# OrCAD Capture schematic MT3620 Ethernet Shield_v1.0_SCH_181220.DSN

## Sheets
1 01 Title, Revision History: rev: v1.0
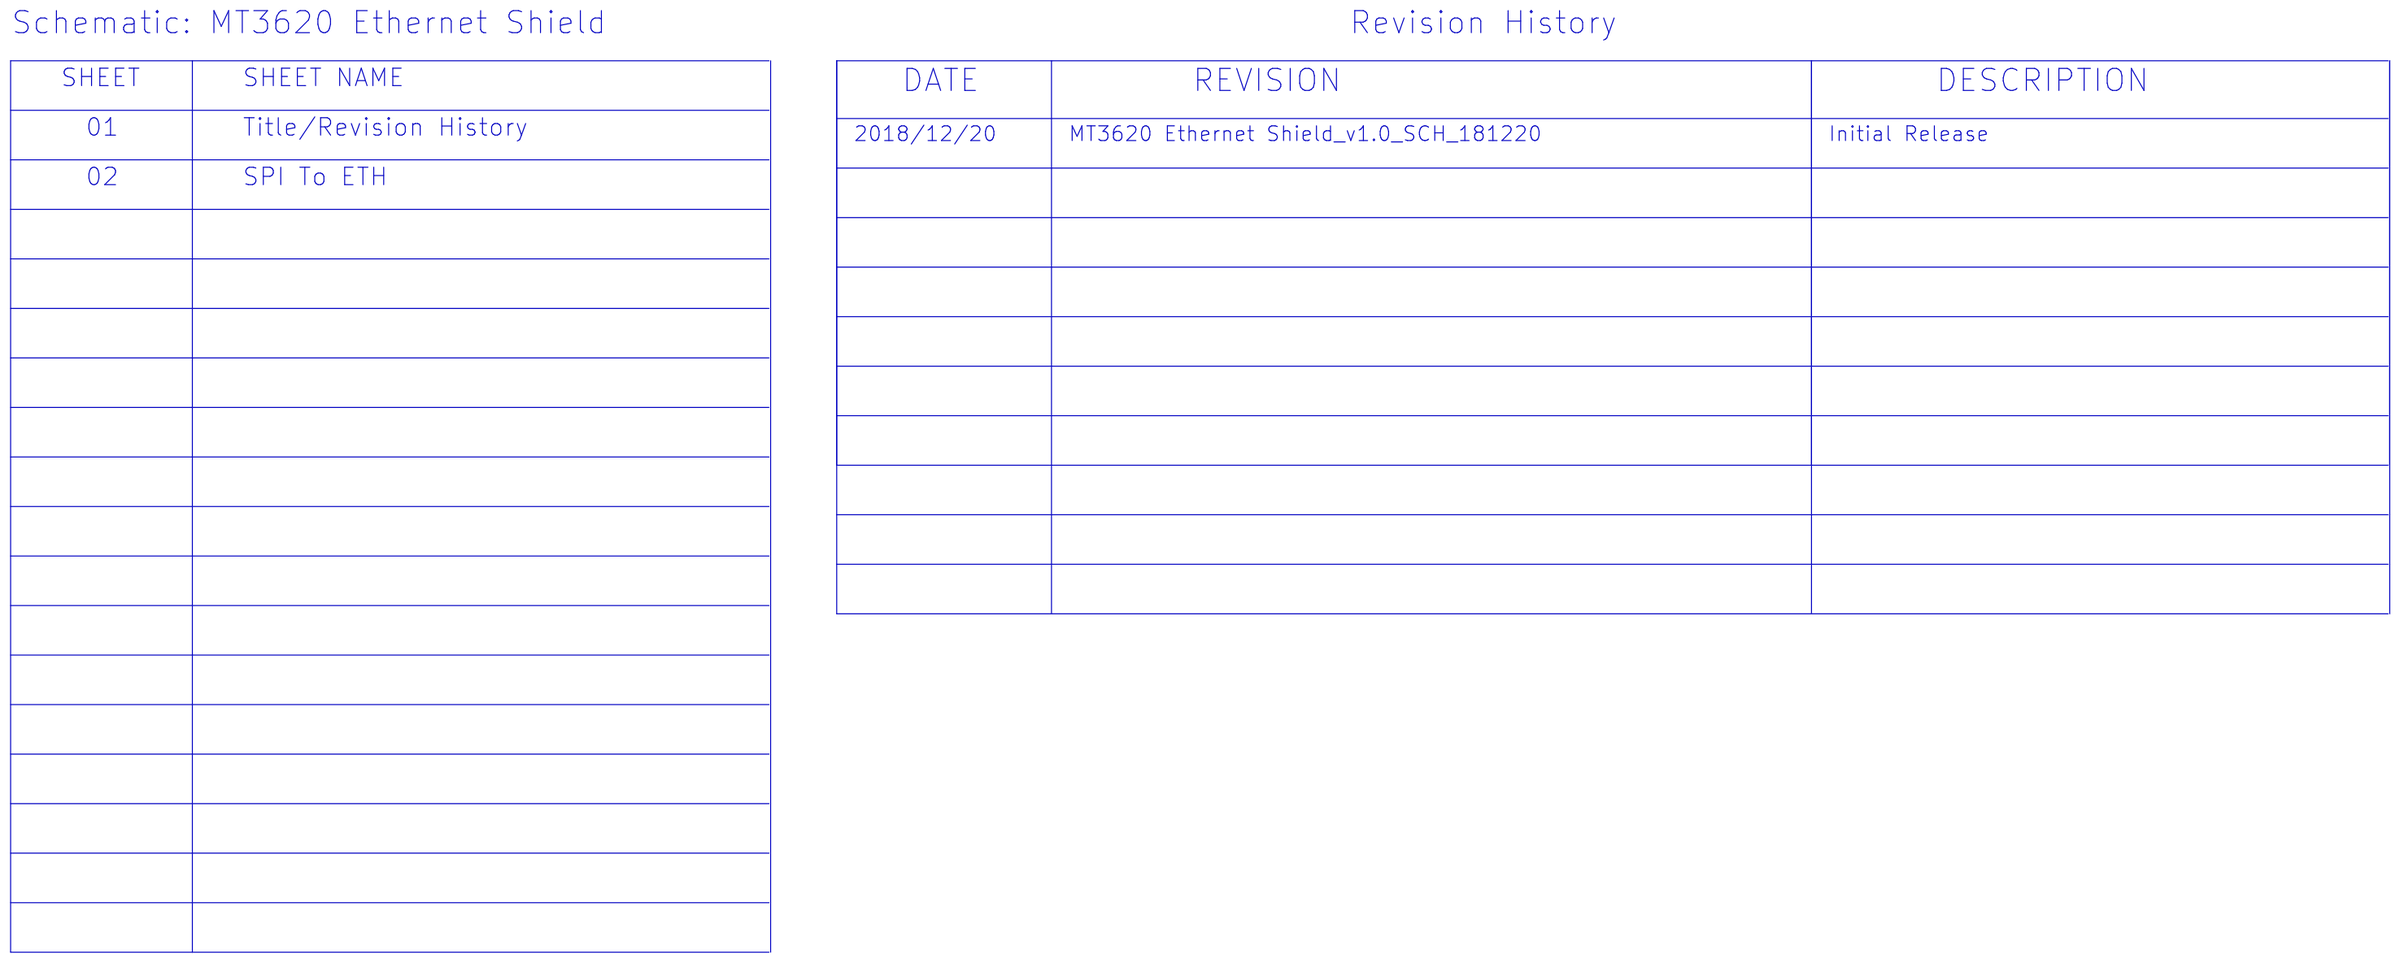
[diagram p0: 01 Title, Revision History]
2 02 SPI To ETH: size A3
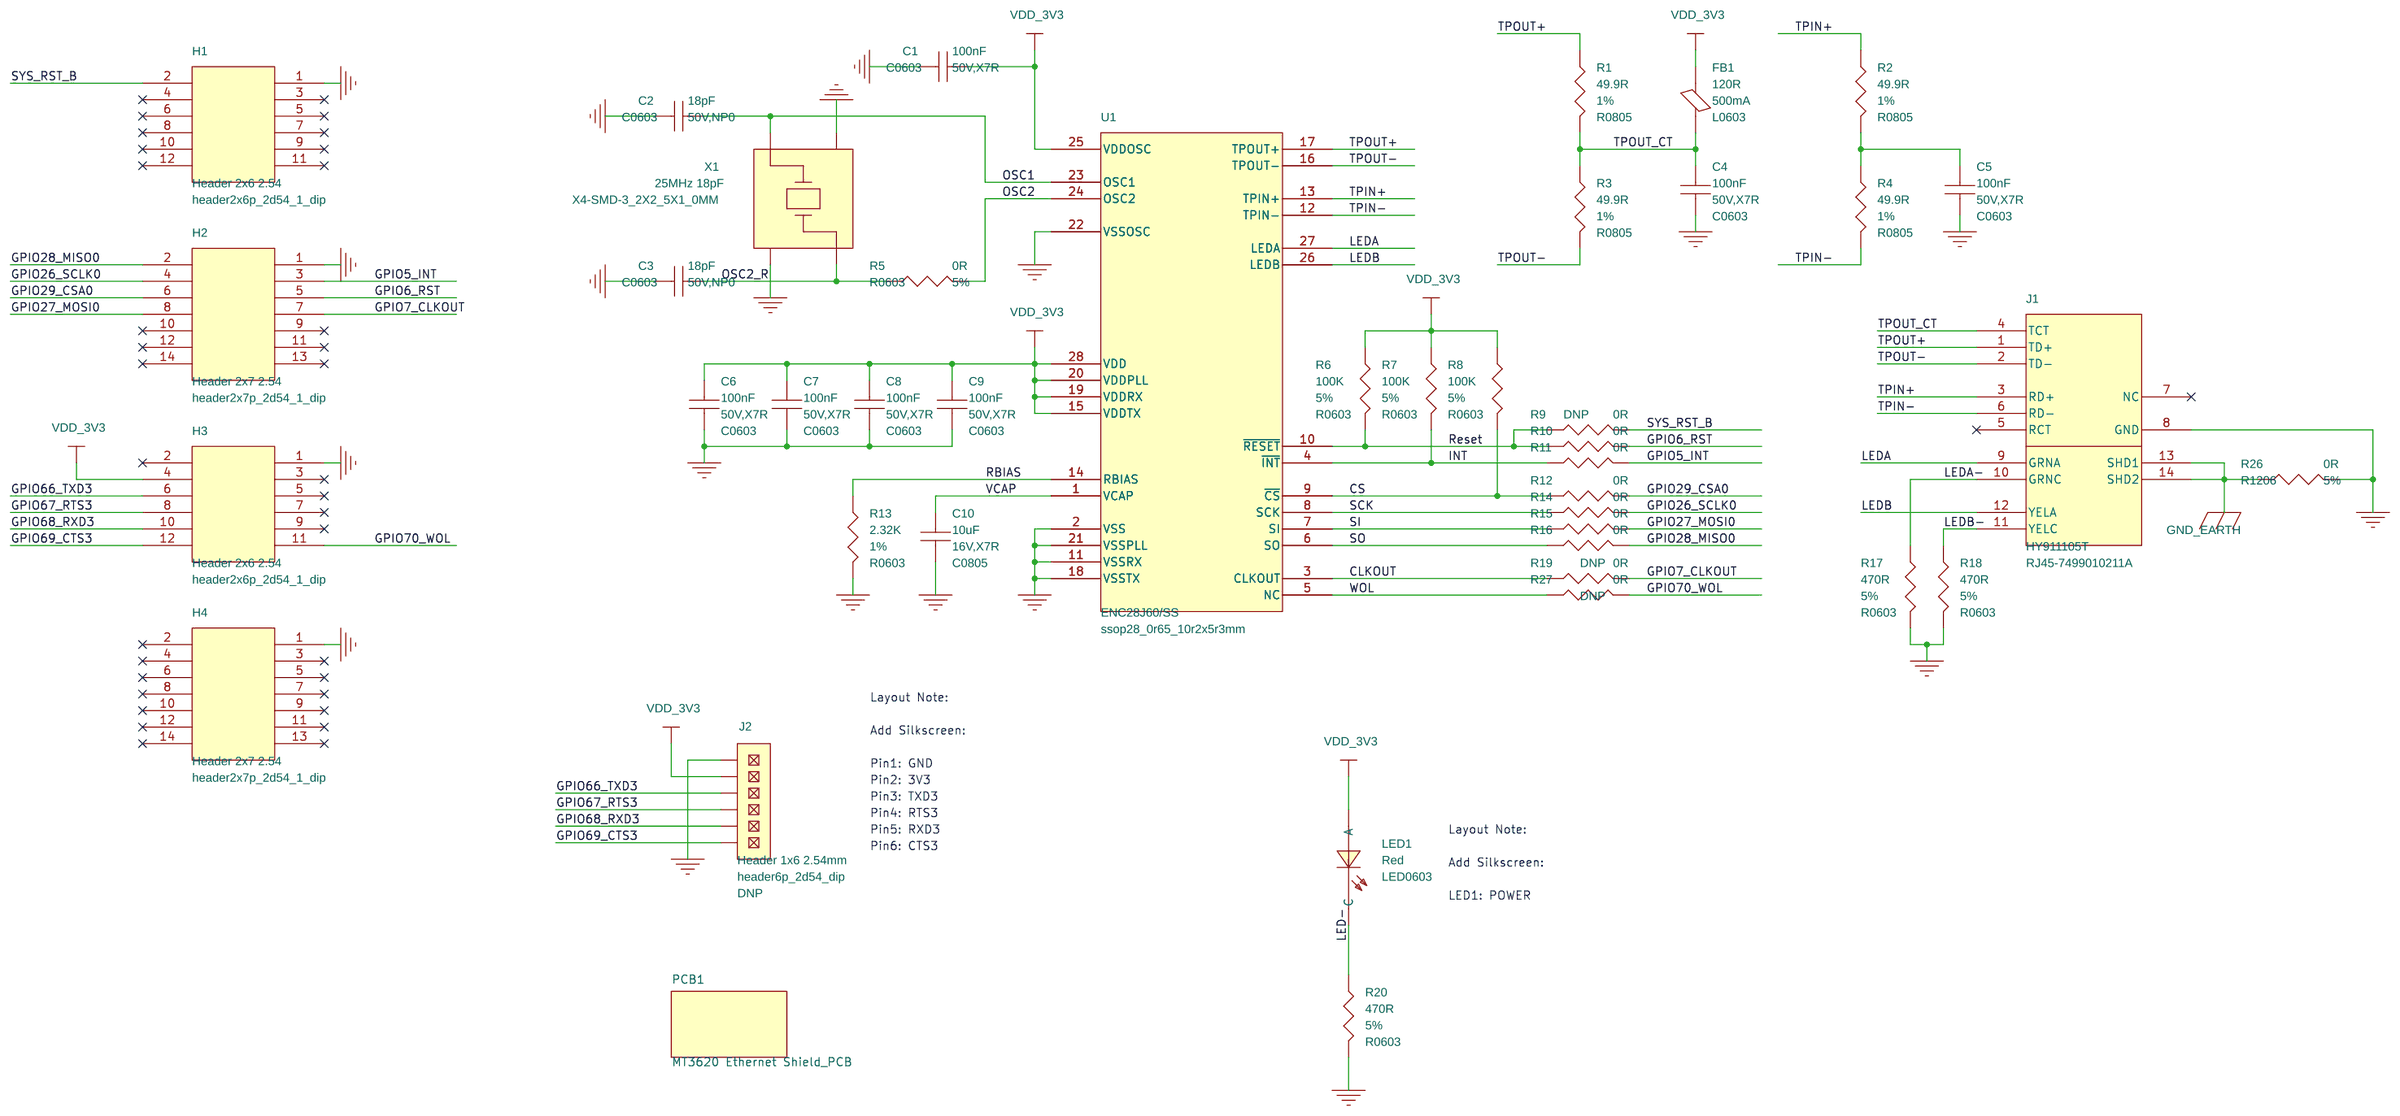
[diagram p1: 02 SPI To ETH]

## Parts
C1  100nF  [C0603]
C2  18pF  [C0603]
C3  18pF  [C0603]
C4  100nF  [C0603]
C5  100nF  [C0603]
C6  100nF  [C0603]
C7  100nF  [C0603]
C8  100nF  [C0603]
C9  100nF  [C0603]
C10  10uF  [C0805]
FB1  120R  [L0603]
H1  Header 2x6 2.54  [header2x6p_2d54_1_dip]
H2  Header 2x7 2.54  [header2x7p_2d54_1_dip]
H3  Header 2x6 2.54  [header2x6p_2d54_1_dip]
H4  Header 2x7 2.54  [header2x7p_2d54_1_dip]
J1  HY911105T  [RJ45-7499010211A]
J2  Header 1x6 2.54mm  [header6p_2d54_dip]
LED1  Red  [LED0603]
PCB1  MT3620 Ethernet Shield_PCB  [NA]
R1  49.9R  [R0805]
R2  49.9R  [R0805]
R3  49.9R  [R0805]
R4  49.9R  [R0805]
R5  0R  [R0603]
R6  100K  [R0603]
R7  100K  [R0603]
R8  100K  [R0603]
R9  0R  [R0603]
R10  0R  [R0603]
R11  0R  [R0603]
R12  0R  [R0603]
R13  2.32K  [R0603]
R14  0R  [R0603]
R15  0R  [R0603]
R16  0R  [R0603]
R17  470R  [R0603]
R18  470R  [R0603]
R19  0R  [R0603]
R20  470R  [R0603]
R26  0R  [R1206]
R27  0R  [R0603]
U1  ENC28J60/SS  [ssop28_0r65_10r2x5r3mm]
X1  25MHz 18pF  [X4-SMD-3_2X2_5X1_0MM]

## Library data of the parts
C1 C4-C9 = CC: SMD CAP Ceramic 100nF-50V-10%-X7R;0603; Manufacturer Part Number: YAGEO;CC0603KRX7R9BB104; PN: 302010138; Part Type: Ceramic; Rating: 50V,X7R; Status: BeagleBone Carrier Board
C2 C3 = CC: SMD CAP Ceramic 18pF-50V-5%-NPO;0603; Manufacturer Part Number: YAGEO;CC0603JRNPO9BN180; PN: 302010083; Part Type: Ceramic; Rating: 50V,NP0; Status: Grove X Gateway
C10 = CC: SMD CAP Ceramic 10uF-16V-10%-X7R;0805; Manufacturer Part Number: YAGEO;CC0805MKX7R7BB106; PN: 302011546; Part Type: Ceramic; Rating: 16V,X7R; Status: Grove X Gateway
FB1 = FB: SMD Ferrite Bead 120R-500mA;0603; Manufacturer Part Number: Murata;BLM18AG121SN1D; PN: 303030001; Part Type: Ferrite Bead; Rating: 500mA; Status: BeagleBone Carrier Board
H1 H3 = Header_2x6: DIP Black Female Header;2*6P-2.54-8.5-10.5; Manufacturer Part Number: 思拓展;FH-2.54-8.5-PC104-2*6P-PBT; PN: 320030886; Part Type: Header; Status: MT3620 Ethernet Shield
H2 H4 = Header_2x7: DIP Black Female Header;2*7P-2.54-8.5-10.5; Manufacturer Part Number: 思拓展;FH-2.54-8.5-PC104-2*7P-PBT; PN: 320030887; Part Type: Header; Status: MT3620 Ethernet Shield
J1 = RJ45_HanRun_HY911105T: DIP RJ45 W/P;12P-21.3*16.04*13.5mm; Manufacturer Part Number: 汉仁;HY911105T; PN: 320140014; Part Type: RJ45; Status: Azure Sphere Ethernet Shield
J2 = Header_1x6: DIP Black Male Header VERT;1*6P-2.54-2.54-11.6/3.0mm; ASSY: DNP; Manufacturer Part Number: P125-1106A1BS116A1; PN: 320020078; Part Type: Header; Status: BeagleBone Carrier Board
LED1 = Single_LED: SMD LED Clear-Red;LED-0603; Manufacturer Part Number: Everlight;EL-19-217/R6C-AL1M2VY/3T(正贴); PN: 304090042; Part Type: LED; Status: BeagleBone Carrier Board
PCB1 = PCB: PCB;MT3620 Ethernet Shield_v1.0-哑光黑油白字-2层; Manufacturer Part Number: 化学沉金-69*50*1.6mm; PN: 319013391
R1-R4 = R: SMD RES 49.9R-1%-1/8W;0805; Manufacturer Part Number: YAGEO;RC0805FR-0749R9L; PN: 301010339; Part Type: RES; Rating: 1%; Status: Azure Sphere Ethernet Shield
R5 R10-R12 R14-R16 = R: SMD RES 0R-5%-1/10W;0603; Manufacturer Part Number: YAGEO;RC0603JR-070RL; PN: 301010292; Part Type: RES; Rating: 5%
R6-R8 = R: SMD RES 100K-5%-1/10W;0603; Manufacturer Part Number: YAGEO;RC0603JR-07100KL; PN: 301010089; Part Type: RES; Rating: 5%; Status: Grove X Gateway
R9 R19 R27 = R: SMD RES 0R-5%-1/10W;0603; ASSY: DNP; Manufacturer Part Number: YAGEO;RC0603JR-070RL; PN: 301010292; Part Type: RES; Rating: 5%
R13 = R: SMD RES 2.32K-1%-1/10W;0603; Manufacturer Part Number: YAGEO;RC0603FR-072K32L; PN: 301012382; Part Type: RES; Rating: 1%; Status: Azure Sphere Ethernet Shield
R17 R18 R20 = R: SMD RES 470R-5%-1/10W;0603; Manufacturer Part Number: YAGEO;RC0603JR-07470RL; PN: 301010088; Part Type: RES; Rating: 5%; Status: IOT Enabling Dongle Board
R26 = R: SMD RES 0R-5%-1/4W;1206; Manufacturer Part Number: YAGEO;RC1206JR-070RL; PN: 301010407; Part Type: RES; Rating: 5%; Status: BeagleBone Carrier Board
U1 = ENC28J60: SMD IC;Stand-Alone Ethernet Controller with SPI Interface;SSOP-28; Manufacturer Part Number: Microchip;ENC28J60/SS; PN: 310070728; Part Type: Transceiver; Status: Azure Sphere Ethernet Shield
X1 = XTAL_4P: SMD Crystal 25MHz-18pF-30ppm;4P-SMD-L3.2*W2.5*H0.8mm; Manufacturer Part Number: Kyocera;CX3225GB25000P0HPQCC; PN: 306010744; Part Type: Crystal; Rating: 30ppm; Status: Combox Pro

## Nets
GND: C1.1 C2.1 C3.1 C4.2 C5.2 C6.2 C7.2 C8.2 C9.2 C10.2 H1.1 H2.1 H3.1 H4.1 J1.8(GND) J2.1 R13.2 R17.2 R18.2 R20.2 R26.2 U1.2(VSS) U1.11(VSSRX) U1.18(VSSTX) U1.21(VSSPLL) U1.22(VSSOSC) X1.2 X1.4
GND_EARTH: J1.13(SHD1) J1.14(SHD2) R26.1
VDD_3V3: C1.2 C6.1 C7.1 C8.1 C9.1 FB1.2 H3.4 J2.2 LED1.1(A) R6.1 R7.1 R8.1 U1.15(VDDTX) U1.19(VDDRX) U1.20(VDDPLL) U1.25(VDDOSC) U1.28(VDD)
CLKOUT: R19.1 U1.3(CLKOUT)
CS: R8.2 R12.1 U1.9(~{CS})
GPIO5_INT: H2.3 R11.2
GPIO6_RST: H2.5 R10.2
GPIO7_CLKOUT: H2.7 R19.2
GPIO26_SCLK0: H2.4 R14.2
GPIO27_MOSI0: H2.8 R15.2
GPIO28_MISO0: H2.2 R16.2
GPIO29_CSA0: H2.6 R12.2
GPIO66_TXD3: H3.6 J2.3
GPIO67_RTS3: H3.8 J2.4
GPIO68_RXD3: H3.10 J2.5
GPIO69_CTS3: H3.12 J2.6
GPIO70_WOL: H3.11 R27.2
INT: R7.2 R11.1 U1.4(~{INT})
LED-: LED1.2(C) R20.1
LEDA: J1.9(GRNA) U1.27(LEDA)
LEDA-: J1.10(GRNC) R17.1
LEDB: J1.12(YELA) U1.26(LEDB)
LEDB-: J1.11(YELC) R18.1
OSC1: C2.2 U1.23(OSC1) X1.1
OSC2: R5.2 U1.24(OSC2)
OSC2_R: C3.2 R5.1 X1.3
RBIAS: R13.1 U1.14(RBIAS)
Reset: R6.2 R9.1 R10.1 U1.10(~{RESET})
SCK: R14.1 U1.8(SCK)
SI: R15.1 U1.7(SI)
SO: R16.1 U1.6(SO)
SYS_RST_B: H1.2 R9.2
TPIN+: J1.3(RD+) R2.1 U1.13(TPIN+)
TPIN-: J1.6(RD-) R4.2 U1.12(TPIN-)
TPOUT+: J1.1(TD+) R1.1 U1.17(TPOUT+)
TPOUT-: J1.2(TD-) R3.2 U1.16(TPOUT-)
TPOUT_CT: C4.1 FB1.1 J1.4(TCT) R1.2 R3.1
VCAP: C10.1 U1.1(VCAP)
WOL: R27.1 U1.5(NC)
N25389849: C5.1 R2.2 R4.1

Not connected (* = marked no-connect by the designer): H1 3* 4* 5* 6* 7* 8* 9* 10* 11* 12*; H2 9* 10* 11* 12* 13* 14*; H3 2* 3* 5* 7* 9*; H4 2* 3* 4* 5* 6* 7* 8* 9* 10* 11* 12* 13* 14*; J1 5(RCT)* 7(NC)*

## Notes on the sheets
sheet 1
- Schematic: MT3620 Ethernet Shield
- Revision History
- SHEET
- SHEET NAME
- DATE
- REVISION
- DESCRIPTION
- 01
- Title/Revision History
- 2018/12/20
- MT3620 Ethernet Shield_v1.0_SCH_181220
- Initial Release
- 02
- SPI To ETH
sheet 2
- Layout Note:
- Add Silkscreen:
- Pin1: GND
- Pin2: 3V3
- Pin3: TXD3
- Pin4: RTS3
- Pin5: RXD3
- Layout Note:
- Pin6: CTS3
- Add Silkscreen:
- LED1: POWER
